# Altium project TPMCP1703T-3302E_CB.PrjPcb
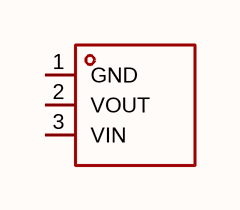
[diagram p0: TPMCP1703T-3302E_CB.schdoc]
1 sheet, 1 parts. Net scope: global (net labels, ports and power ports of the same name join across sheets).

## Sheet TPMCP1703T-3302E_CB.schdoc
size 127 x 101 mm

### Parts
U?  tpmcp1703t-3302e/cb  [SOT-23-3_L2.9-W1.6-P1.90-LS2.8-BR]  (value not drawn)

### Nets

Not connected (* = marked no-connect by the designer): U? 1(GND) 2(VOUT) 3(VIN)

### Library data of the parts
U? = tpmcp1703t-3302e/cb: 输出极性:正极;工作电压:24V;输出电压:3.3V;输出电流:300mA;电源纹波抑制比(PSRR):-;输出类型:固定；可调;; Manufacturer: TECH PUBLIC(台舟); AddInBom: yes; ModelId: 89cb27a44ab2466697082bb9fd73a7d0; ModelName: SOT-23-3L_L2.9-W1.6-H1.1-LS2.8-P0.95; ModelTransform: 114.173,110.236,0,90,0,0,0,0,0; Output Configuration: 正极; Voltage - Supply: 24V; Output Voltage: 3.3V; Output Current: 300mA; Voltage Dropout: 90mV@(40mA); standby current: 2uA; Output Type: 固定；可调; Number of Outputs: 1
